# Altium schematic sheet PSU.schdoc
size 262 x 95 mm
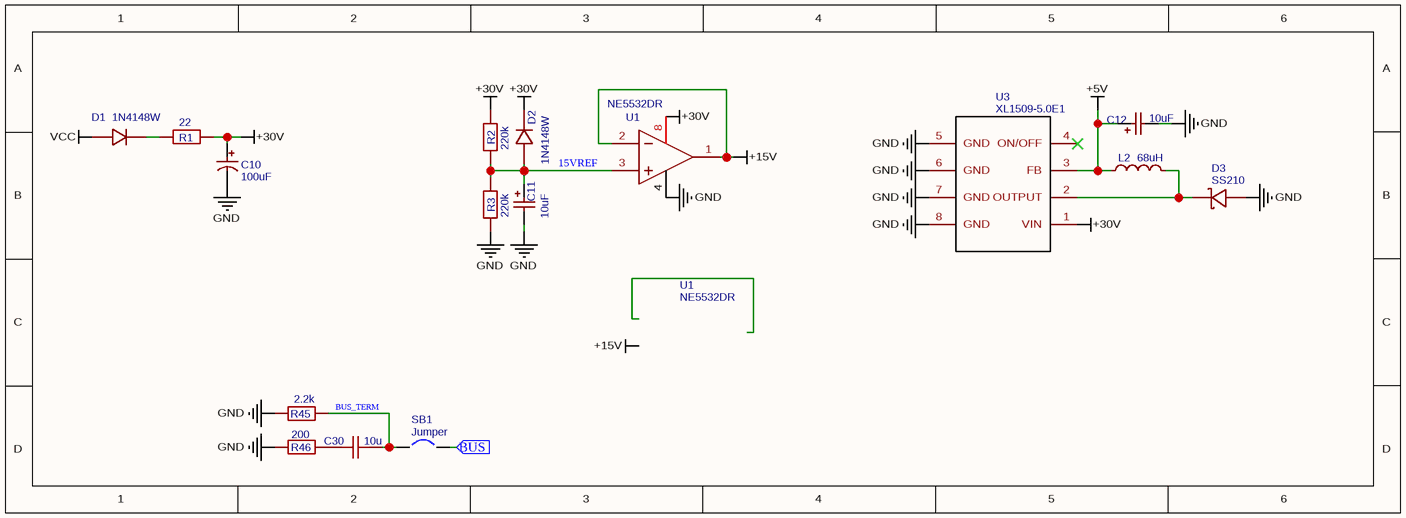
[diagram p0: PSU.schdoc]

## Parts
(Parts that share a designator on the sheet are numbered #1, #2 ... from top to bottom, then left to right.)
C10  100uF  [CAP-SMD_BD8.0-L8.3-W8.3-FD]
C11  10uF  [CAP-SMD_L3.2-W1.6-RD-C7171]
C12  10uF  [CAP-SMD_L3.2-W1.6-RD-C7171]
C30  10u  [C1206]
D1  1N4148W  [SOD-123FL_L2.6-W1.6-LS3.4-RD]
D2  1N4148W  [SOD-123FL_L2.6-W1.6-LS3.4-RD]
D3  SS210  [SMA_L4.3-W2.6-LS5.2-RD]
L2  68uH  [IND-SMD_L6.0-W6.0_SWRH5D]
R1  22  [R1206]
R2  220k  [R0805]
R3  220k  [R0805]
R45  2.2k  [R0805]
R46  200  [R0805]
SB1  Jumper  [PAD-JUMPER-2-NC_BY_PASTE_YES_SILK]
U1#1  NE5532DR  [SOIC-8_L4.9-W3.9-P1.27-LS6.0-BL]
U1#2  NE5532DR  [SOIC-8_L4.9-W3.9-P1.27-LS6.0-BL]
U3  XL1509-5.0E1  [SOIC-8_L5.0-W4.0-P1.27-LS6.0-BL]

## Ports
BUS (in)

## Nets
+5V: C12.1 L2.1 U3.3(FB)
+15V: U1#1.1(OUT1) U1#1.2(IN1-)
+30V: C10.1 D2.1 R1.2 R2.2 U1#1.8(VCC+) U3.1(VIN)
GND: C10.2 C11.2 C12.2 D3.2(A) R3.1 R45.1 R46.2 U1#1.4(VCC-/GND) U3.5(GND) U3.6(GND) U3.7(GND) U3.8(GND)
VCC: D1.2
15VREF: C11.1 D2.2 R2.1 R3.2 U1#1.3(IN1+)
BUS: SB1.2 ; port BUS
BUS_TERM: C30.2 R45.2 SB1.1
NetC30_1: C30.1 R46.1
NetD1_1: D1.1 R1.1
NetD3_1: D3.1(K) L2.2 U3.2(OUTPUT)

Not connected (* = marked no-connect by the designer): U3 4(ON/OFF)*

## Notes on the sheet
- Labels drawn without touching a wire or pin: +15V

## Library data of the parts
C10 = 100uF: BOM_Manufacturer: HONOR(荣誉); BOM_Manufacturer Part: RVT1H101M0810; nameAlias: Capacitance
C11 C12 = 10uF: BOM_Manufacturer: Kyocera AVX; BOM_Manufacturer Part: TAJA106K016RNJ; nameAlias: Capacitance
C30 = 10u: BOM_Manufacturer Part: CL31A106KBHNNNE; BOM_Manufacturer: SAMSUNG(三星); nameAlias: Value(F); Contributor: LCEDA_Lib
D1 D2 = 1N4148W: BOM_Manufacturer: Tak Cheong; Contributor: LCEDA_Lib
D3 = SS210: BOM_Manufacturer: MDD
L2 = 68uH: BOM_Manufacturer: YJYCOIN(益嘉源); BOM_Manufacturer Part: YNR6028-680M; nameAlias: Inductance; Contributor: LCSC
R1 = 22: BOM_Manufacturer Part: 1206W4F220JT5E; BOM_Manufacturer: UNI-ROYAL(厚声); nameAlias: Value(Ω); Contributor: LCEDA_Lib
R2 R3 = 220k: BOM_Manufacturer Part: 0805W8F2203T5E; BOM_Manufacturer: UNI-ROYAL(厚声); nameAlias: Value(Ω); Contributor: LCEDA_Lib
R45 = 2.2k: BOM_Manufacturer Part: 0805W8F2201T5E; BOM_Manufacturer: UNI-ROYAL(厚声); nameAlias: Value(Ω); Contributor: LCEDA_Lib
R46 = 200: BOM_Manufacturer Part: 0805W8F2000T5E; BOM_Manufacturer: UNI-ROYAL(厚声); nameAlias: Value(Ω); Contributor: LCEDA_Lib
SB1 = Jumper: BOM_Manufacturer: NONE; BOM_Manufacturer Part: 0603WAF0000T5E; nameAlias: Value; Contributor: Levente Mitnyik
U1#1 U1#2 = NE5532DR: BOM_Manufacturer: TI(德州仪器); subpart_no: 2; SMT Type: Basic
U3 = XL1509-5.0E1: BOM_Manufacturer: XLSEMI(芯龙)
